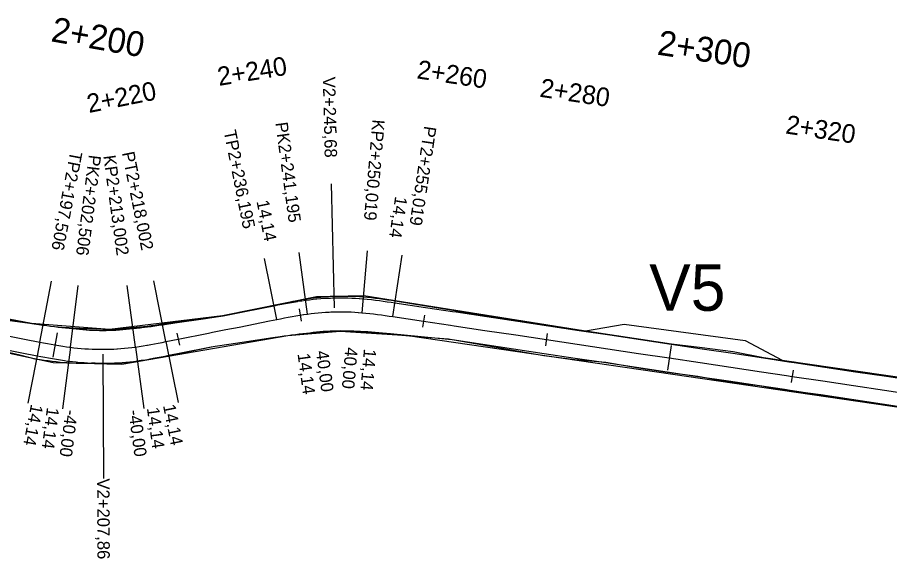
# Model space of a CAD drawing. Extents: x -636600 to -628587, y -1090963 to -1085869.
# Drawn here: x -633130.8 to -632990.4, y -1089276.8 to -1089189.7 of the extents above; entities that cross this region are included whole.
import ezdxf

# ---------------------------------------------------------------- set-up
doc = ezdxf.new("R2010")
doc.units = 0
for name, color, linetype in [('01_PARCELY_NÁVRH_PC', 7, 'Continuous'), ('03_PC_OBJEKTY_NÁVRH', 7, 'Continuous'), ('HEKTOMETRY100', 7, 'Continuous'), ('HEKTOMETRY20', 7, 'Continuous'), ('HL_BODY', 7, 'Continuous'), ('POLOMERY', 7, 'Continuous'), ('situace_osa', 7, 'Continuous'), ('situace_těleso', 7, 'Continuous'), ('situace_vozovka', 7, 'Continuous'), ('VRCHOLY', 7, 'Continuous')]:
    doc.layers.add(name, color=color, linetype=linetype)

msp = doc.modelspace()

# ---------------------------------------------------------------- linework, layer by layer
at = {"layer": '01_PARCELY_NÁVRH_PC'}
for points in [[(-633176.45, -1089229.84), (-633128.52, -1089238.97), (-633115.96, -1089239.94), (-633097.79, -1089237.72), (-633082.64, -1089234.66), (-633075.04, -1089234.5), (-633039.36, -1089240.17), (-633033.12, -1089239.09), (-633013.62, -1089241.75), (-633007.71, -1089244.88), (-632938.73, -1089254.9)], [(-632940.33, -1089259.62), (-633067.93, -1089241), (-633078.82, -1089240.31), (-633087.24, -1089240.97), (-633113.95, -1089245.58), (-633125.04, -1089245.35), (-633144.94, -1089241.08)]]:
    msp.add_lwpolyline(points, dxfattribs=at)
at = {"layer": 'HEKTOMETRY100'}
for points in [[(-633124.39, -1089240.48), (-633125.08, -1089244.41)], [(-633025.56, -1089242.57), (-633026.16, -1089246.53)]]:
    msp.add_lwpolyline(points, dxfattribs=at)
at = {"layer": 'HEKTOMETRY20'}
for points in [[(-633085.45, -1089236.66), (-633085.13, -1089238.64)], [(-633065.27, -1089237.64), (-633065.57, -1089239.62)], [(-633105.11, -1089240.54), (-633104.71, -1089242.5)], [(-633045.49, -1089240.6), (-633045.79, -1089242.58)], [(-633005.93, -1089246.52), (-633006.23, -1089248.5)]]:
    msp.add_lwpolyline(points, dxfattribs=at)
at = {"layer": 'HL_BODY'}
for points in [[(-633084.11, -1089237.48), (-633085.45, -1089227.57)], [(-633075.3, -1089237.26), (-633074.45, -1089227.3)], [(-633070.35, -1089237.9), (-633068.87, -1089228.01)], [(-633089.03, -1089238.35), (-633090.99, -1089228.55)], [(-633127.18, -1089241.99), (-633125.29, -1089232.17)], [(-633106.87, -1089241.92), (-633108.83, -1089232.11)], [(-633122.26, -1089242.83), (-633120.98, -1089232.91)], [(-633111.79, -1089242.79), (-633113.13, -1089232.88)]]:
    msp.add_lwpolyline(points, dxfattribs=at)
at = {"layer": 'POLOMERY'}
for points in [[(-633084.11, -1089237.48), (-633085.45, -1089227.57)], [(-633075.3, -1089237.26), (-633074.45, -1089227.3)], [(-633070.35, -1089237.9), (-633068.87, -1089228.01)], [(-633089.03, -1089238.35), (-633090.99, -1089228.55)], [(-633127.18, -1089241.99), (-633129.08, -1089251.81)], [(-633106.87, -1089241.92), (-633104.91, -1089251.72)], [(-633122.26, -1089242.83), (-633123.53, -1089252.75)], [(-633111.79, -1089242.79), (-633110.45, -1089252.7)]]:
    msp.add_lwpolyline(points, dxfattribs=at)
at = {"layer": 'situace_osa'}
msp.add_lwpolyline([(-633134.56, -1089240.57), (-633129.65, -1089241.51), (-633127.18, -1089241.99), (-633126.57, -1089242.1), (-633125.96, -1089242.22), (-633125.34, -1089242.34), (-633124.73, -1089242.44), (-633124.73, -1089242.45), (-633124.11, -1089242.55), (-633123.49, -1089242.65), (-633122.88, -1089242.74), (-633122.41, -1089242.81), (-633122.26, -1089242.83), (-633121.68, -1089242.9), (-633121.1, -1089242.96), (-633120.52, -1089243.01), (-633119.94, -1089243.06), (-633119.78, -1089243.07), (-633119.35, -1089243.09), (-633118.77, -1089243.12), (-633118.19, -1089243.14), (-633117.61, -1089243.15), (-633117.02, -1089243.15), (-633116.44, -1089243.15), (-633115.86, -1089243.13), (-633115.27, -1089243.11), (-633114.78, -1089243.08), (-633114.69, -1089243.08), (-633114.11, -1089243.04), (-633113.53, -1089242.99), (-633112.95, -1089242.93), (-633112.37, -1089242.87), (-633111.96, -1089242.82), (-633111.79, -1089242.79), (-633111.17, -1089242.7), (-633110.56, -1089242.61), (-633109.94, -1089242.5), (-633109.82, -1089242.48), (-633109.32, -1089242.39), (-633108.71, -1089242.28), (-633108.1, -1089242.16), (-633107.48, -1089242.04), (-633106.87, -1089241.92), (-633104.91, -1089241.52), (-633100.01, -1089240.54), (-633099.39, -1089240.42), (-633097.23, -1089239.99), (-633095.1, -1089239.57), (-633090.2, -1089238.59), (-633089.03, -1089238.35), (-633088.42, -1089238.23), (-633087.8, -1089238.11), (-633087.19, -1089237.99), (-633086.58, -1089237.88), (-633085.96, -1089237.76), (-633085.34, -1089237.66), (-633085.29, -1089237.65), (-633084.73, -1089237.56), (-633084.66, -1089237.55), (-633084.11, -1089237.48), (-633083.52, -1089237.4), (-633082.94, -1089237.33), (-633082.35, -1089237.28), (-633081.77, -1089237.23), (-633081.18, -1089237.19), (-633080.59, -1089237.16), (-633080.32, -1089237.14), (-633080.01, -1089237.13), (-633079.42, -1089237.12), (-633078.83, -1089237.11), (-633078.24, -1089237.12), (-633077.65, -1089237.13), (-633077.07, -1089237.15), (-633076.48, -1089237.18), (-633075.92, -1089237.21), (-633075.89, -1089237.21), (-633075.32, -1089237.26), (-633075.3, -1089237.26), (-633074.68, -1089237.32), (-633074.06, -1089237.39), (-633073.44, -1089237.46), (-633072.82, -1089237.54), (-633072.2, -1089237.63), (-633071.58, -1089237.71), (-633070.96, -1089237.8), (-633070.36, -1089237.89), (-633070.35, -1089237.9), (-633065.42, -1089238.63), (-633061.07, -1089239.28), (-633060.47, -1089239.37), (-633055.53, -1089240.11), (-633050.58, -1089240.85), (-633045.64, -1089241.59), (-633040.69, -1089242.33), (-633035.75, -1089243.07), (-633030.8, -1089243.81), (-633025.86, -1089244.55), (-633020.91, -1089245.29), (-633015.97, -1089246.03), (-633011.02, -1089246.77), (-633006.97, -1089247.37), (-633006.08, -1089247.51), (-633001.13, -1089248.25), (-632996.19, -1089248.99), (-632991.24, -1089249.73), (-632986.3, -1089250.47)], dxfattribs=at)
at = {"layer": 'situace_těleso'}
for points in [[(-633134.07, -1089238.06), (-633129.14, -1089238.89), (-633126.65, -1089239.21), (-633126.04, -1089239.31), (-633125.43, -1089239.41), (-633124.82, -1089239.5), (-633124.22, -1089239.55), (-633124.22, -1089239.55), (-633123.62, -1089239.59), (-633123.02, -1089239.63), (-633122.43, -1089239.66), (-633121.99, -1089239.68), (-633121.85, -1089239.69), (-633121.32, -1089239.73), (-633120.78, -1089239.76), (-633120.25, -1089239.79), (-633119.71, -1089239.8), (-633119.56, -1089239.81), (-633119.17, -1089239.81), (-633118.64, -1089239.8), (-633118.1, -1089239.84), (-633117.57, -1089239.88), (-633117.03, -1089239.91), (-633116.5, -1089239.93), (-633115.96, -1089239.94), (-633115.42, -1089239.93), (-633114.97, -1089239.9), (-633114.89, -1089239.89), (-633114.35, -1089239.85), (-633113.82, -1089239.8), (-633113.29, -1089239.75), (-633112.75, -1089239.69), (-633112.38, -1089239.65), (-633112.22, -1089239.64), (-633111.64, -1089239.59), (-633111.06, -1089239.54), (-633110.47, -1089239.48), (-633110.35, -1089239.46), (-633109.87, -1089239.41), (-633109.27, -1089239.33), (-633108.66, -1089239.25), (-633108.05, -1089239.17), (-633107.44, -1089239.08), (-633105.45, -1089238.8), (-633100.49, -1089238.11), (-633099.87, -1089238.02), (-633097.69, -1089237.71), (-633095.56, -1089237.29), (-633090.65, -1089236.33), (-633089.48, -1089236.1), (-633088.87, -1089235.97), (-633088.25, -1089235.83), (-633087.63, -1089235.69), (-633087, -1089235.55), (-633086.37, -1089235.42), (-633085.73, -1089235.29), (-633085.67, -1089235.28), (-633085.09, -1089235.17), (-633085.02, -1089235.16), (-633084.43, -1089235.06), (-633083.82, -1089234.97), (-633083.2, -1089234.89), (-633082.58, -1089234.81), (-633081.96, -1089234.75), (-633081.33, -1089234.69), (-633080.71, -1089234.65), (-633080.42, -1089234.63), (-633080.09, -1089234.62), (-633079.46, -1089234.59), (-633078.84, -1089234.58), (-633078.21, -1089234.58), (-633077.58, -1089234.58), (-633076.96, -1089234.6), (-633076.33, -1089234.63), (-633075.74, -1089234.66), (-633075.71, -1089234.66), (-633075.1, -1089234.71), (-633075.08, -1089234.71), (-633074.42, -1089234.77), (-633073.77, -1089234.84), (-633073.12, -1089234.92), (-633072.48, -1089235), (-633071.84, -1089235.09), (-633071.21, -1089235.18), (-633070.59, -1089235.27), (-633069.99, -1089235.36), (-633069.97, -1089235.37), (-633065.05, -1089236.16), (-633060.71, -1089236.87), (-633060.11, -1089236.97), (-633055.18, -1089237.77), (-633050.24, -1089238.57), (-633045.31, -1089239.36), (-633040.35, -1089240.02), (-633035.4, -1089240.76), (-633030.46, -1089241.53), (-633025.52, -1089242.26), (-633020.56, -1089242.89), (-633015.59, -1089243.51), (-633010.68, -1089244.46), (-633006.62, -1089245.04), (-633005.73, -1089245.18), (-633000.79, -1089245.97), (-632995.85, -1089246.75), (-632990.91, -1089247.48), (-632985.95, -1089248.16)], [(-632986.66, -1089252.85), (-632991.59, -1089252.05), (-632996.53, -1089251.25), (-633001.47, -1089250.5), (-633006.43, -1089249.83), (-633007.32, -1089249.71), (-633011.36, -1089249.02), (-633016.33, -1089248.45), (-633021.25, -1089247.53), (-633026.21, -1089246.87), (-633031.15, -1089246.14), (-633036.08, -1089245.3), (-633041.07, -1089244.83), (-633046.03, -1089244.2), (-633050.96, -1089243.34), (-633055.88, -1089242.48), (-633060.81, -1089241.62), (-633061.4, -1089241.51), (-633065.8, -1089241.18), (-633070.78, -1089240.77), (-633070.79, -1089240.77), (-633071.4, -1089240.72), (-633072.01, -1089240.66), (-633072.62, -1089240.61), (-633073.22, -1089240.56), (-633073.82, -1089240.52), (-633074.41, -1089240.48), (-633075, -1089240.45), (-633075.58, -1089240.43), (-633075.59, -1089240.43), (-633076.12, -1089240.41), (-633076.15, -1089240.41), (-633076.66, -1089240.38), (-633077.2, -1089240.35), (-633077.74, -1089240.33), (-633078.28, -1089240.31), (-633078.82, -1089240.31), (-633079.36, -1089240.31), (-633079.9, -1089240.32), (-633080.19, -1089240.33), (-633080.45, -1089240.33), (-633080.99, -1089240.36), (-633081.53, -1089240.39), (-633082.07, -1089240.43), (-633082.61, -1089240.47), (-633083.15, -1089240.52), (-633083.69, -1089240.58), (-633084.2, -1089240.65), (-633084.26, -1089240.65), (-633084.8, -1089240.7), (-633084.85, -1089240.7), (-633085.44, -1089240.76), (-633086.03, -1089240.82), (-633086.64, -1089240.89), (-633087.24, -1089240.97), (-633087.86, -1089241.05), (-633088.47, -1089241.14), (-633089.66, -1089241.31), (-633094.61, -1089242.05), (-633096.76, -1089242.37), (-633098.93, -1089242.7), (-633099.55, -1089242.82), (-633104.45, -1089243.81), (-633106.41, -1089244.21), (-633107.03, -1089244.33), (-633107.65, -1089244.46), (-633108.27, -1089244.58), (-633108.9, -1089244.7), (-633109.41, -1089244.79), (-633109.54, -1089244.81), (-633110.18, -1089244.93), (-633110.82, -1089245.03), (-633111.48, -1089245.13), (-633111.65, -1089245.15), (-633112.09, -1089245.21), (-633112.7, -1089245.29), (-633113.31, -1089245.35), (-633113.93, -1089245.41), (-633114.55, -1089245.46), (-633114.64, -1089245.47), (-633115.16, -1089245.5), (-633115.78, -1089245.53), (-633116.4, -1089245.53), (-633117.02, -1089245.49), (-633117.63, -1089245.44), (-633118.25, -1089245.4), (-633118.86, -1089245.41), (-633119.48, -1089245.43), (-633119.93, -1089245.44), (-633120.1, -1089245.44), (-633120.72, -1089245.44), (-633121.34, -1089245.43), (-633121.96, -1089245.4), (-633122.58, -1089245.37), (-633122.75, -1089245.36), (-633123.25, -1089245.32), (-633123.9, -1089245.26), (-633124.55, -1089245.19), (-633125.2, -1089245.12), (-633125.2, -1089245.12), (-633125.84, -1089245.03), (-633126.47, -1089244.95), (-633127.1, -1089244.86), (-633127.72, -1089244.78), (-633130.16, -1089244.18), (-633135.03, -1089243.04)]]:
    msp.add_lwpolyline(points, dxfattribs=at)
at = {"layer": 'situace_vozovka'}
for points in [[(-633134.1, -1089238.23), (-633129.14, -1089238.91), (-633126.66, -1089239.25), (-633126.04, -1089239.34), (-633125.43, -1089239.42), (-633124.82, -1089239.5), (-633124.23, -1089239.57), (-633124.22, -1089239.58), (-633123.62, -1089239.64), (-633123.03, -1089239.71), (-633122.45, -1089239.76), (-633122.01, -1089239.8), (-633121.87, -1089239.81), (-633121.34, -1089239.88), (-633120.8, -1089239.94), (-633120.26, -1089239.98), (-633119.73, -1089240.03), (-633119.58, -1089240.04), (-633119.19, -1089240.06), (-633118.65, -1089240.08), (-633118.11, -1089240.1), (-633117.57, -1089240.11), (-633117.03, -1089240.11), (-633116.49, -1089240.11), (-633115.96, -1089240.1), (-633115.42, -1089240.07), (-633114.96, -1089240.05), (-633114.88, -1089240.04), (-633114.34, -1089240.01), (-633113.81, -1089239.96), (-633113.27, -1089239.91), (-633112.73, -1089239.85), (-633112.36, -1089239.8), (-633112.2, -1089239.79), (-633111.62, -1089239.74), (-633111.03, -1089239.68), (-633110.44, -1089239.61), (-633110.33, -1089239.6), (-633109.85, -1089239.54), (-633109.25, -1089239.46), (-633108.64, -1089239.38), (-633108.03, -1089239.29), (-633107.41, -1089239.2), (-633105.43, -1089238.91), (-633100.48, -1089238.19), (-633099.85, -1089238.1), (-633097.67, -1089237.78), (-633095.54, -1089237.36), (-633090.64, -1089236.38), (-633089.47, -1089236.15), (-633088.85, -1089236.02), (-633088.24, -1089235.9), (-633087.61, -1089235.78), (-633086.98, -1089235.66), (-633086.35, -1089235.55), (-633085.71, -1089235.44), (-633085.65, -1089235.43), (-633085.06, -1089235.34), (-633085, -1089235.33), (-633084.41, -1089235.25), (-633083.79, -1089235.17), (-633083.18, -1089235.1), (-633082.56, -1089235.04), (-633081.94, -1089234.98), (-633081.32, -1089234.94), (-633080.7, -1089234.91), (-633080.41, -1089234.9), (-633080.08, -1089234.88), (-633079.46, -1089234.87), (-633078.83, -1089234.86), (-633078.21, -1089234.87), (-633077.59, -1089234.88), (-633076.97, -1089234.9), (-633076.35, -1089234.93), (-633075.77, -1089234.97), (-633075.73, -1089234.97), (-633075.13, -1089235.02), (-633075.11, -1089235.02), (-633074.46, -1089235.08), (-633073.81, -1089235.15), (-633073.16, -1089235.23), (-633072.52, -1089235.31), (-633071.89, -1089235.4), (-633071.26, -1089235.49), (-633070.63, -1089235.58), (-633070.03, -1089235.67), (-633070.01, -1089235.67), (-633065.09, -1089236.41), (-633060.74, -1089237.06), (-633060.14, -1089237.15), (-633055.2, -1089237.89), (-633050.25, -1089238.63), (-633045.31, -1089239.37), (-633040.36, -1089240.11), (-633035.42, -1089240.85), (-633030.47, -1089241.59), (-633025.53, -1089242.32), (-633020.58, -1089243.06), (-633015.64, -1089243.8), (-633010.69, -1089244.54), (-633006.64, -1089245.15), (-633005.75, -1089245.28), (-633000.8, -1089246.02), (-632995.86, -1089246.76), (-632990.91, -1089247.5), (-632985.97, -1089248.24)], [(-633134.98, -1089242.78), (-633130.07, -1089243.72), (-633127.61, -1089244.2), (-633126.99, -1089244.31), (-633126.37, -1089244.43), (-633125.75, -1089244.55), (-633125.12, -1089244.66), (-633125.12, -1089244.66), (-633124.48, -1089244.77), (-633123.84, -1089244.87), (-633123.2, -1089244.97), (-633122.7, -1089245.04), (-633122.54, -1089245.06), (-633121.93, -1089245.13), (-633121.32, -1089245.2), (-633120.71, -1089245.26), (-633120.09, -1089245.3), (-633119.92, -1089245.31), (-633119.48, -1089245.34), (-633118.86, -1089245.37), (-633118.25, -1089245.39), (-633117.63, -1089245.4), (-633117.02, -1089245.4), (-633116.4, -1089245.4), (-633115.78, -1089245.38), (-633115.17, -1089245.36), (-633114.64, -1089245.33), (-633114.55, -1089245.32), (-633113.94, -1089245.28), (-633113.33, -1089245.23), (-633112.71, -1089245.17), (-633112.1, -1089245.1), (-633111.67, -1089245.05), (-633111.49, -1089245.02), (-633110.84, -1089244.93), (-633110.19, -1089244.83), (-633109.55, -1089244.72), (-633109.43, -1089244.7), (-633108.92, -1089244.61), (-633108.29, -1089244.49), (-633107.66, -1089244.37), (-633107.04, -1089244.24), (-633106.43, -1089244.12), (-633104.47, -1089243.73), (-633099.57, -1089242.75), (-633098.95, -1089242.63), (-633096.77, -1089242.31), (-633094.62, -1089242), (-633089.66, -1089241.28), (-633088.48, -1089241.1), (-633087.86, -1089241.01), (-633087.25, -1089240.93), (-633086.65, -1089240.84), (-633086.04, -1089240.76), (-633085.45, -1089240.69), (-633084.86, -1089240.63), (-633084.81, -1089240.62), (-633084.27, -1089240.57), (-633084.22, -1089240.56), (-633083.7, -1089240.49), (-633083.16, -1089240.42), (-633082.62, -1089240.36), (-633082.08, -1089240.3), (-633081.54, -1089240.26), (-633081, -1089240.22), (-633080.45, -1089240.19), (-633080.2, -1089240.18), (-633079.91, -1089240.17), (-633079.37, -1089240.16), (-633078.82, -1089240.15), (-633078.28, -1089240.16), (-633077.74, -1089240.17), (-633077.19, -1089240.19), (-633076.65, -1089240.21), (-633076.14, -1089240.24), (-633076.11, -1089240.25), (-633075.58, -1089240.26), (-633075.56, -1089240.26), (-633074.98, -1089240.28), (-633074.39, -1089240.31), (-633073.8, -1089240.35), (-633073.2, -1089240.39), (-633072.6, -1089240.44), (-633071.99, -1089240.49), (-633071.37, -1089240.55), (-633070.77, -1089240.61), (-633070.75, -1089240.61), (-633065.79, -1089241.09), (-633061.4, -1089241.51), (-633060.81, -1089241.6), (-633055.86, -1089242.34), (-633050.92, -1089243.08), (-633045.97, -1089243.82), (-633041.03, -1089244.56), (-633036.08, -1089245.3), (-633031.14, -1089246.04), (-633026.19, -1089246.78), (-633021.25, -1089247.51), (-633016.3, -1089248.25), (-633011.36, -1089248.99), (-633007.31, -1089249.6), (-633006.41, -1089249.73), (-633001.47, -1089250.47), (-632996.52, -1089251.21), (-632991.58, -1089251.95), (-632986.63, -1089252.69)]]:
    msp.add_lwpolyline(points, dxfattribs=at)
at = {"layer": 'VRCHOLY'}
for points in [[(-633079.73, -1089236.49), (-633080.21, -1089216.5)], [(-633117.02, -1089243.94), (-633116.95, -1089263.94)]]:
    msp.add_lwpolyline(points, dxfattribs=at)

# ---------------------------------------------------------------- texts
at = {"layer": '03_PC_OBJEKTY_NÁVRH'}
msp.add_text('V5', height=7.5, dxfattribs=at).set_placement((-633029.09, -1089236.96))
at = {"layer": 'HEKTOMETRY100'}
for s, rotation, p in [('2+200', 349.9909, (-633125.52, -1089193.56)), ('2+300', 351.4944, (-633027.93, -1089195.71))]:
    msp.add_text(s, height=4, rotation=rotation, dxfattribs=at).set_placement(p)
at = {"layer": 'HEKTOMETRY20'}
for s, rotation, p in [('2+240', 9.222, (-633098.33, -1089200.76)), ('2+260', 351.4944, (-633066.6, -1089199.53)), ('2+220', 11.296, (-633119.27, -1089205.13)), ('2+280', 351.4944, (-633046.82, -1089202.49)), ('2+320', 351.4944, (-633007.26, -1089208.4))]:
    msp.add_text(s, height=3, rotation=rotation, dxfattribs=at).set_placement(p)
at = {"layer": 'HL_BODY'}
for s, rotation, p in [('PK2+241,195', 277.715, (-633089.28, -1089206.71)), ('KP2+250,019', 265.0754, (-633073.62, -1089206.11)), ('TP2+236,195', 281.296, (-633097.59, -1089208.07)), ('PT2+255,019', 261.4944, (-633065.3, -1089207.13)), ('PT2+218,002', 281.296, (-633113.96, -1089211.54)), ('TP2+197,506', 259.0999, (-633122.27, -1089211.18)), ('PK2+202,506', 262.6809, (-633119.28, -1089211.78)), ('KP2+213,002', 277.715, (-633116.97, -1089212.03))]:
    msp.add_text(s, height=2, rotation=rotation, dxfattribs=at).set_placement(p)
at = {"layer": 'POLOMERY'}
for s, rotation, p in [('14,14', 281.296, (-633092.31, -1089219.35)), ('14,14', 261.4944, (-633069.97, -1089218.46)), ('40,00', 277.715, (-633082.73, -1089243.5)), ('40,00', 265.0754, (-633077.99, -1089242.77)), ('14,14', 265.0754, (-633075, -1089243.03)), ('14,14', 277.715, (-633085.7, -1089243.9)), ('14,14', 259.0999, (-633128.58, -1089251.9)), ('14,14', 262.6809, (-633126.01, -1089252.43)), ('-40,00', 262.6809, (-633123.04, -1089252.81)), ('-40,00', 277.715, (-633112.93, -1089253.04)), ('14,14', 277.715, (-633109.95, -1089252.63)), ('14,14', 281.296, (-633107.36, -1089252.21))]:
    msp.add_text(s, height=2, rotation=rotation, dxfattribs=at).set_placement(p)
at = {"layer": 'VRCHOLY'}
for s, rotation, p in [('V2+245,68', 271.3952, (-633081.63, -1089199.32)), ('V2+207,86', 270.198, (-633117.95, -1089263.95))]:
    msp.add_text(s, height=2, rotation=rotation, dxfattribs=at).set_placement(p)

doc.saveas('drawing.dxf')
